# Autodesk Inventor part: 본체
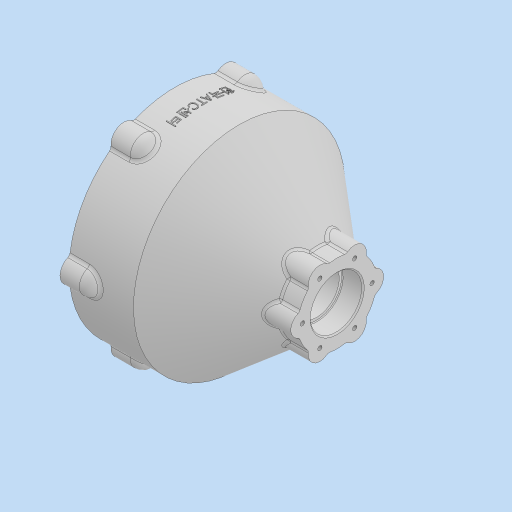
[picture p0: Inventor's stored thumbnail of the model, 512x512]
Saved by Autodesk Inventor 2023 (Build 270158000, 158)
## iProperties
Created: 2026-05
Part Number: 본체
Material: 일반
Document SubType Name: Modeling
Designer: home
Density: 1 g/cm^3
Appearance: 기본값
Author: home
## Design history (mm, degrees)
sketch "스케치3"
  geometry: L1 (0, 0)-(126, 0); L2 (0, 0)-(0, 82); L3 (0, 82)-(50, 82); L4 (50, 82)-(111.375, 30.5); L5 (111.375, 30.5)-(126, 30.5); L6 (126, 30.5)-(126, 0)
  constraints: 12 end point, 2 perpendicular, 1 horizontal, 1 parallel, 1 vertical
  dimensions: "d8" = 126 distance of L1.start L1.end; "d11" = 61 diameter of L5 L1; "d12" = 164 diameter of L3 L1; "d13" = 50 distance from line of L3.end L2; "d14" = 40 deg angle of L4 L3
revolve "회전2" sketch "스케치3" stored, may be unused: angle "d15" = 90 deg
sketch "스케치4"
  geometry: L1 (0, 0)-(13.5, 23.383); L2 (0, 0)-(27, 0); C1 r 30.5 at (0, 0) reference; C2 r 27 at (0, 0); C3 r 9 at (13.5, 23.383); 2 further points
  constraints: 4 end point, 2 centre point, 2 coincident, 1 equal length, 1 horizontal
  dimensions: "d16" = 54 diameter of C2; "d17" = 27 distance of L1.start L1.end; "d18" = 60 deg angle of L2 L1; "d19" = 18 diameter of C3
extrude "돌출1" join sketch "스케치4" stored distance "d20" = 10; taper "d21" = 0 deg
sketch "스케치5"
  geometry: A1 r 9 centre (0, 0) between (8.72, 2.227) and (-8.72, 2.227) reference; 2 further points
  constraints: 1 coincident
hole "구멍1" sketch "스케치5" at (0, 0) diameter "d22" = 3.45873; stored, may be unused: countersink angle "d26" = 90 deg, drill point angle "d28" = 118 deg; dims "d23" = 8, "d24" = 7, "d25" = 2, "d27" = 10
sketch "스케치8"
  geometry: L1 (0, 0)-(39.5, 68.416); L2 (0, 0)-(79, 0); C1 r 82 at (0, 0) reference; C2 r 79 at (0, 0); C3 r 10 at (39.5, 68.416); 2 further points
  constraints: 4 end point, 2 centre point, 2 coincident, 1 equal length, 1 horizontal
  dimensions: "d38" = 158 diameter of C2; "d39" = 79 distance of L1.start L1.end; "d40" = 60 deg angle of L2 L1; "d42" = 20 diameter of C3
extrude "돌출3" join sketch "스케치8" distance "d43" = 15; taper "d44" = 0 deg
sketch "스케치9"
  geometry: L1 (0, 0)-(-39.5, 68.416); L2 (0, 0)-(79, 0); L3 (-39.5, 68.416)-(47.103, 118.416); A1 r 82 centre (0, 0) between (-32.31, 75.366) and (-49.114, 65.664) reference; A2 r 10 centre (-39.5, 68.416) between (-32.31, 75.366) and (-49.114, 65.664) reference
  constraints: 6 end point, 1 equal length, 1 horizontal
  dimensions: "d45" = 79 distance of L1.start L1.end; "d46" = 120 deg angle of L2 L1; "d49" = 100 distance of L1.end L3.end; "d50" = 90 deg angle of L1 L3
revolve "회전3" sketch "스케치9" stored, may be unused: angle "d51" = 90 deg
sketch "스케치12"
  geometry: A1 r 10 centre (0, 0) between (9.702, 2.424) and (-9.702, 2.424) reference; 2 further points
  constraints: 1 coincident
hole "구멍2" sketch "스케치12" at (0, 0) diameter "d52" = 4.917; stored, may be unused: countersink angle "d56" = 90 deg, drill point angle "d58" = 118 deg; dims "d53" = 12, "d54" = 4, "d55" = 2, "d57" = 14
sketch "스케치14"
  geometry: L1 (0, 0)-(126, 0); L2 (126, -8.72)-(126, 8.72) reference; L3 (0, 0)-(0, 73); L4 (0, 73)-(37, 73); L5 (14, 70.875)-(0, 70.875) reference; L6 (37, 73)-(37, 68); L7 (37, 68)-(42, 68); L8 (42, 68)-(42, 56); L9 (42, 56)-(62, 56); L10 (62, 56)-(62, 40); L11 (62, 40)-(78, 40); L12 (78, 40)-(78, 37); L13 (78, 37)-(82, 37); L14 (82, 37)-(82, 20); L15 (82, 20)-(94, 20); L16 (94, 20)-(94, 17.5); L17 (94, 17.5)-(110, 17.5); L18 (110, 17.5)-(110, 20); L19 (110, 20)-(126, 20); L20 (126, 20.951)-(126, 32.383) reference; L21 (126, 20)-(126, 0); 2 further points
  constraints: 36 end point, 12 perpendicular, 3 vertical, 1 horizontal, 1 midpoint, 1 parallel, 1 point on line
  dimensions: "d62" = 146 diameter of L4 L1; "d63" = 37 distance between parallel lines of L6 L3; "d64" = 40 diameter of L19 L1; "d65" = 35 diameter of L17 L1; "d66" = 16 distance between parallel lines of L18 L21; "d67" = 40 diameter of L15 L1; "d68" = 12 distance between parallel lines of L16 L14; "d69" = 136 diameter of L7 L1; "d70" = 112 diameter of L9 L1; "d71" = 80 diameter of L11 L1; "d72" = 74 diameter of L13 L1; "d73" = 16 distance between parallel lines of L12 L10; "d74" = 20 distance between parallel lines of L14 L10; "d75" = 5 distance between parallel lines of L6 L8; "d76" = 25 distance between parallel lines of L10 L6
revolve "회전4" sketch "스케치14" stored, may be unused: angle "d77" = 90 deg
chamfer "모따기1" distance "d78" = 1; stored, may be unused: second distance "d79" = 2, angle "d80" = 45 deg
fillet "모깎기1" dims "d81" = 0.6
sketch "스케치16"
  geometry: L1 (0, 0)-(31, 53.694); L2 (0, 0)-(62, 0); C1 r 56 at (0, 0) reference; C2 r 62 at (0, 0); 1 further point
  constraints: 4 end point, 2 coincident, 1 centre point, 1 equal length, 1 horizontal
  dimensions: "d87" = 124 diameter of C2; "d88" = 62 distance of L1.start L1.end; "d89" = 60 deg angle of L2 L1
hole "구멍3" sketch "스케치16" at (31, 53.694) diameter "d90" = 3.242; stored, may be unused: countersink angle "d94" = 90 deg, drill point angle "d96" = 118 deg; dims "d91" = 8, "d92" = 4, "d93" = 2, "d95" = 10
fillet "모깎기2" dims "d100" = 3
fillet "모깎기3" dims "d101" = 1
fillet "모깎기4" dims "d102" = 3
fillet "모깎기5" dims "d103" = 3
fillet "모깎기6" dims "d104" = 3
node "작업 평면4"
sketch "스케치18"
  geometry: L1 (0, 30.625)-(0, -30.625) reference; 2 further points
  constraints: 1 horizontal alignment, 1 other
  dimensions: "d106" = 20 distance from line of point (-20, 0) L1
feature "엠보싱1" sketch "스케치18" dims "d107" = 0.5, "d108" = 0
feature "ʹ耀Ͷ耀͸耀ͺ耀ͼ耀;耀΀耀΂耀" dims "d8" = 126, "d11" = 61, "d12" = 164, "d13" = 50, "d14" = 40 deg, "d15" = 90 deg, "d16" = 54, "d17" = 27, "d18" = 60 deg, "d19" = 18, "d20" = 10, "d21" = 0, "d22" = 3.45873, "d23" = 8, "d24" = 7, "d25" = 2, "d26" = 90 deg, "d27" = 10, "d28" = 118 deg, "d29" = 60, "d30" = 360 deg, "d38" = 158, "d39" = 79, "d40" = 60 deg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
node "솔리드2"
pattern_circular "원형 패턴1" dims angle "d30" = 360 deg
pattern_circular "원형 패턴2" dims angle "d60" = 360 deg
pattern_circular "원형 패턴3" dims angle "d98" = 360 deg
feature "A9D066F2-1C7D-4E18-AEED-F7BC21143FA4" dims "d22" = 3.45873, "d23" = 8, "d24" = 7, "d25" = 2, "d26" = 90 deg, "d27" = 10, "d28" = 118 deg
